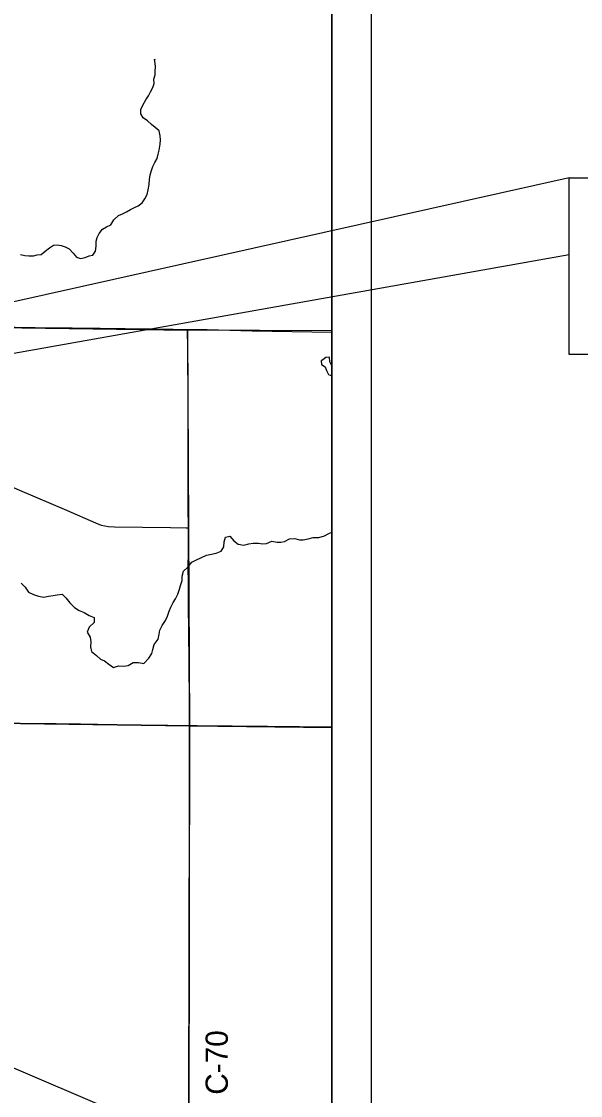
# Model space of a CAD drawing. Extents: x 0 to 45.9, y 0 to 22.
# Drawn here: x 8.107 to 9.535, y 16.738 to 19.483 of the extents above; entities that cross this region are included whole.
import ezdxf

# ---------------------------------------------------------------- set-up
doc = ezdxf.new("R2010")
doc.units = 0
for name, color, linetype in [('Default', 7, 'Continuous'), ('GM_X_County_Road', 7, 'Continuous'), ('GM_X_County_Road_Text', 7, 'Continuous'), ('GM_X_Minor_Lake', 7, 'Continuous'), ('GM_X_Minor_River', 7, 'Continuous'), ('GM_X_Section', 7, 'Continuous'), ('GM_X_Township_Road', 7, 'Continuous'), ('SH_Border', 7, 'Continuous'), ('SH_Cut_Line', 7, 'Continuous'), ('SH_Text', 7, 'Continuous')]:
    doc.layers.add(name, color=color, linetype=linetype)

msp = doc.modelspace()

# ---------------------------------------------------------------- linework, layer by layer
at = {"layer": 'Default'}
msp.add_lwpolyline([(8.9, 14.1), (8.9, 19.7611)], dxfattribs=at)
for points in [[(8.9, 17.6782), (8.9, 18.6923), (8.5306, 18.6937), (8.5357, 17.6824)], [(8.9, 16.6634), (8.9, 17.6782), (8.5357, 17.6824), (8.5339, 16.6685)]]:
    msp.add_lwpolyline(points, close=True, dxfattribs=at)
at = {"layer": 'GM_X_County_Road'}
for points in [[(7.5646, 18.7065), (7.6024, 18.707), (7.6707, 18.7061), (7.7889, 18.705), (7.9163, 18.7034), (8.0219, 18.7023), (8.0903, 18.7015), (8.1929, 18.7), (8.2363, 18.6995), (8.3078, 18.6991), (8.4353, 18.6974), (8.4943, 18.6963), (8.5313, 18.6958)], [(8.5313, 18.6958), (8.5813, 18.6952), (8.6963, 18.6925), (8.9, 18.6885)], [(8.5332, 18.1889), (8.5329, 18.2423), (8.5326, 18.3853), (8.5326, 18.5034), (8.5314, 18.6526), (8.5313, 18.6899), (8.5313, 18.6958)], [(7.5612, 18.5152), (7.5666, 18.5129), (7.6355, 18.4843), (7.7843, 18.4208), (7.9787, 18.3375), (8.1074, 18.2827), (8.1417, 18.268), (8.2218, 18.2337), (8.296, 18.2014), (8.3105, 18.1959), (8.3195, 18.1935), (8.3287, 18.192), (8.3442, 18.191), (8.4873, 18.1896), (8.5278, 18.189), (8.5332, 18.1889)], [(8.536, 17.6836), (8.536, 17.691), (8.5356, 17.7501), (8.5356, 17.7687), (8.535, 17.8185), (8.5351, 17.8558), (8.5343, 17.9143), (8.534, 17.9484), (8.5336, 17.9672), (8.5338, 17.969), (8.5337, 17.975), (8.5336, 17.9998), (8.5333, 18.0279), (8.5332, 18.0341), (8.5331, 18.0528), (8.533, 18.0838), (8.5331, 18.1304), (8.5332, 18.1739), (8.5332, 18.1889)], [(7.738, 17.6948), (7.8006, 17.6939), (7.8969, 17.6926), (8.1423, 17.6888), (8.1951, 17.6883), (8.2573, 17.6874), (8.3442, 17.6861), (8.4809, 17.6842), (8.536, 17.6836)], [(8.5341, 16.6724), (8.5341, 16.6809), (8.534, 16.7088), (8.5347, 16.8674), (8.5349, 16.9637), (8.5352, 17.116), (8.5351, 17.1813), (8.535, 17.2279), (8.5349, 17.259), (8.5356, 17.3305), (8.536, 17.4113), (8.5357, 17.4517), (8.536, 17.489), (8.536, 17.5885), (8.5363, 17.66), (8.536, 17.6836)], [(8.536, 17.6836), (8.5555, 17.6834), (8.7357, 17.6815), (8.9, 17.6803)]]:
    msp.add_lwpolyline(points, dxfattribs=at)
at = {"layer": 'GM_X_Minor_Lake'}
for points in [[(8.8766, 18.6182), (8.8728, 18.6155), (8.8733, 18.606), (8.883, 18.6004), (8.8857, 18.5908), (8.8911, 18.5808), (8.9, 18.5772)], [(8.9, 18.6032), (8.8997, 18.603), (8.8947, 18.613), (8.8939, 18.6248), (8.8844, 18.6239), (8.8766, 18.6182)]]:
    msp.add_lwpolyline(points, dxfattribs=at)
at = {"layer": 'GM_X_Minor_River'}
for points in [[(8.3241, 18.9575), (8.3352, 18.9628), (8.3431, 18.9755), (8.3548, 18.9866), (8.3647, 18.9909), (8.3747, 18.9963), (8.3851, 19.0025), (8.3951, 19.0075), (8.4047, 19.0114), (8.4148, 19.0195), (8.4222, 19.0296), (8.4282, 19.0408), (8.4304, 19.0521), (8.4327, 19.0657), (8.4338, 19.0786), (8.4353, 19.0904), (8.439, 19.1016), (8.4419, 19.1122), (8.4475, 19.1223), (8.4531, 19.1324), (8.4557, 19.1437), (8.4586, 19.1535), (8.4609, 19.169), (8.462, 19.1804), (8.4608, 19.1903), (8.4588, 19.2029), (8.4485, 19.2115), (8.4385, 19.2198), (8.4289, 19.2284), (8.4174, 19.2367), (8.4116, 19.2468), (8.4119, 19.2574), (8.4164, 19.269), (8.4243, 19.2821), (8.4314, 19.2929), (8.4362, 19.3027), (8.4426, 19.3143), (8.4455, 19.3244), (8.4451, 19.3351), (8.448, 19.3464), (8.4487, 19.3559), (8.449, 19.3665), (8.4485, 19.376), (8.4468, 19.3856), (8.4491, 19.3866)], [(8.104, 18.8876), (8.1153, 18.8846), (8.1255, 18.8836), (8.1372, 18.8836), (8.1471, 18.886), (8.1574, 18.8869), (8.1671, 18.8961), (8.1787, 18.9041), (8.1887, 18.9107), (8.1982, 18.9123), (8.208, 18.9102), (8.2181, 18.9072), (8.2286, 18.9016), (8.2385, 18.8907), (8.2473, 18.8802), (8.2575, 18.8773), (8.2696, 18.8796), (8.2796, 18.8842), (8.2891, 18.8855), (8.2958, 18.8956), (8.2973, 18.9084), (8.2973, 18.921), (8.3002, 18.9308), (8.3054, 18.9409), (8.3137, 18.9517), (8.3241, 18.9575)], [(8.4322, 17.8558), (8.4401, 17.8679), (8.4424, 17.8778), (8.4458, 17.8907), (8.4556, 17.9044), (8.4589, 17.9169), (8.4604, 17.9268), (8.4665, 17.9389), (8.4751, 17.9522), (8.4796, 17.9629), (8.4838, 17.9758), (8.4887, 17.9857), (8.4939, 17.9978), (8.5003, 18.0073), (8.506, 18.0195), (8.5101, 18.0316), (8.5127, 18.0415), (8.5169, 18.054), (8.5172, 18.065), (8.5206, 18.0779), (8.5316, 18.0882), (8.5417, 18.1007), (8.5535, 18.1072), (8.5664, 18.1126), (8.5792, 18.1191), (8.5921, 18.1218), (8.6039, 18.1241), (8.6168, 18.1294), (8.6239, 18.1401), (8.6243, 18.1526), (8.6276, 18.1647), (8.639, 18.1678), (8.6493, 18.1553), (8.6603, 18.1466), (8.6744, 18.1444), (8.6872, 18.1475), (8.6986, 18.1494), (8.7123, 18.1491), (8.7229, 18.1476), (8.7331, 18.1488), (8.7464, 18.1545), (8.7597, 18.1523), (8.7692, 18.1519), (8.779, 18.1535), (8.7911, 18.1607), (8.8048, 18.1612), (8.8173, 18.1582), (8.8268, 18.1582), (8.8389, 18.1609), (8.8518, 18.164), (8.8666, 18.1636), (8.881, 18.1686), (8.8924, 18.1743), (8.9, 18.1779)], [(8.1057, 18.047), (8.116, 18.0371), (8.1248, 18.0239), (8.1373, 18.0182), (8.1498, 18.0137), (8.1635, 18.0115), (8.176, 18.0142), (8.1881, 18.0161), (8.1976, 18.0173), (8.2105, 18.0189), (8.22, 18.0098), (8.2299, 17.9973), (8.2425, 17.9848), (8.2543, 17.9777), (8.2672, 17.972), (8.2797, 17.9645), (8.2923, 17.9596), (8.2923, 17.9471), (8.2798, 17.9349), (8.2742, 17.922), (8.2822, 17.9091), (8.2838, 17.8977), (8.2827, 17.8848), (8.2857, 17.8723), (8.2987, 17.8621), (8.309, 17.8527), (8.3185, 17.8489), (8.3302, 17.8402), (8.3416, 17.8316), (8.3549, 17.8358), (8.3674, 17.8354), (8.3792, 17.837), (8.3924, 17.8446), (8.4061, 17.8443), (8.4194, 17.8421), (8.4322, 17.8558)]]:
    msp.add_lwpolyline(points, dxfattribs=at)
at = {"layer": 'GM_X_Section'}
for points in [[(7.5622, 18.7071), (8.5306, 18.6937), (8.5357, 17.6824), (7.5472, 17.6966)], [(7.5472, 17.6966), (8.5357, 17.6824), (8.5339, 16.6685), (7.5363, 16.6862)]]:
    msp.add_lwpolyline(points, close=True, dxfattribs=at)
at = {"layer": 'GM_X_Township_Road'}
for points in [[(7.738, 17.6948), (7.8006, 17.6939), (7.8969, 17.6926), (8.1423, 17.6888), (8.1951, 17.6883), (8.2573, 17.6874), (8.3442, 17.6861), (8.4809, 17.6842), (8.536, 17.6836)], [(8.536, 17.6836), (8.5555, 17.6834), (8.7357, 17.6815), (8.9, 17.6803)]]:
    msp.add_lwpolyline(points, dxfattribs=at)
at = {"layer": 'SH_Border'}
for points in [[(9.5057, 19.0827), (5.2104, 18.1241), (9.5057, 18.8875)], [(9.5057, 19.0827), (10.9834, 19.0827), (10.9834, 18.6317), (9.5057, 18.6317)], [(9.4963, 16.2045), (5.2331, 18.0284), (9.4963, 15.9502)]]:
    msp.add_lwpolyline(points, close=True, dxfattribs=at)
at = {"layer": 'SH_Cut_Line'}
for p, q in [((9, 21), (9, 14)), ((8.9, 20.9), (8.9, 14.1))]:
    msp.add_line(p, q, dxfattribs=at)
at = {"layer": 'SH_Text'}
msp.add_lwpolyline([(8.9, 14.1), (8.9, 19.7611)], dxfattribs=at)

# ---------------------------------------------------------------- texts
at = {"layer": 'GM_X_County_Road_Text'}
msp.add_text('C-70', height=0.05682, rotation=90, dxfattribs=at).set_placement((8.6339, 16.74))

doc.saveas('drawing.dxf')
